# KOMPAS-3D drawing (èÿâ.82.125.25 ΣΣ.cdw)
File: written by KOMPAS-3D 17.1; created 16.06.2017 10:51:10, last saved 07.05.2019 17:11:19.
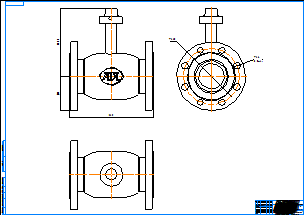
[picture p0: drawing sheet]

Sheet 1: A0, landscape

Title block, sheet 1: name: КШГ.82.125.25 фф; material: Внимание! Данный продукт является объектом авторского права ООО «Торговый Дом АДЛ». / Запрещается изменение, копирование, распространение / (в том числе путем копирования на другие сайты и ресурсы в Интернете) / или любое иное использование информации и объектов без предварительного / согласия правообладателя (ООО «Торговый Дом АДЛ»).; scale: 1:1; sheets: 1; organisation: ООО "Торговый дом АДЛ"; sheet format: A0; stored path: C:\Users\tra\Desktop\2д чертежи\Шаровые краны БИВАЛ\КШ_Бивал_серия_82_85\KOMPAS 2D\КШГ.82.125.25 фф.cdw

Views: Спереди 1, Проекционный вид 2, Проекционный вид 3
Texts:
  Klimkovich
  ADL
Dimensions and other numbers on the sheet: 325; 266,9; 135; 220; 26; 8 Отв.; 1:1; 1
